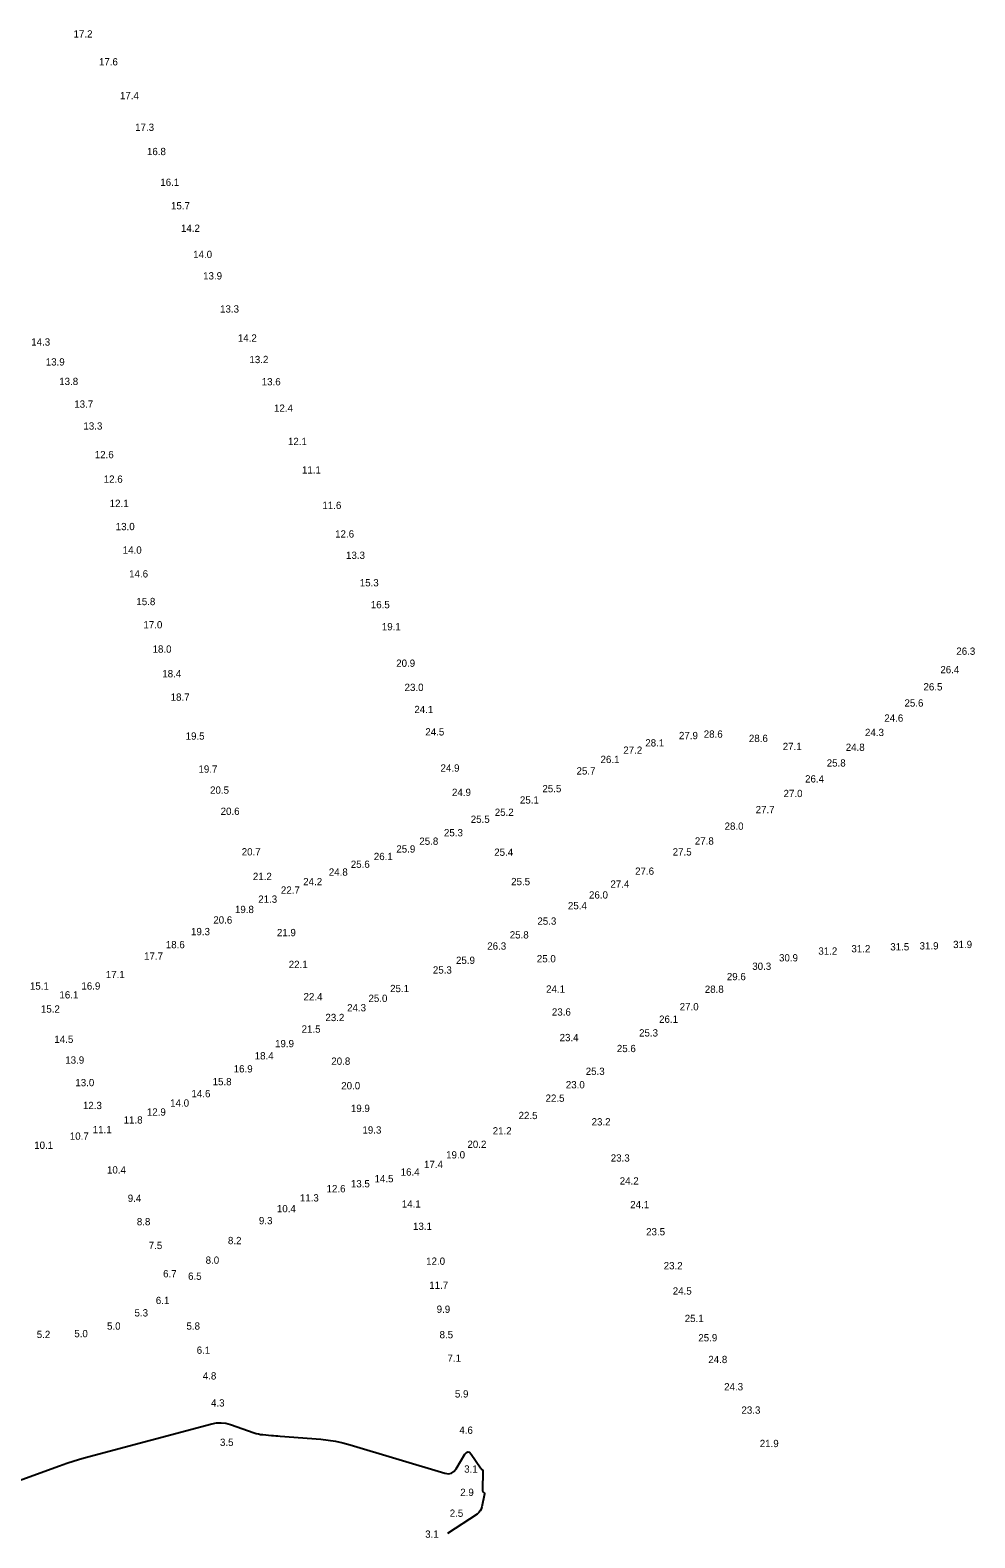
# Model space of a CAD drawing. Extents: x 837127 to 848654, y 3074248 to 3079868.
# Drawn here: x 848248 to 848654, y 3078663 to 3079310 of the extents above; entities that cross this region are included whole.
import ezdxf

# ---------------------------------------------------------------- set-up
doc = ezdxf.new("R2010")
doc.units = 0
doc.layers.add('V-HYDS-MAJR', color=7, linetype='Continuous')
doc.layers.add('V-HYDS-SOUN', color=7, linetype='Continuous')

msp = doc.modelspace()

# ---------------------------------------------------------------- linework, layer by layer
at = {"layer": 'V-HYDS-MAJR'}
msp.add_lwpolyline([(848242.88, 3078687.16), (848260.67, 3078693.63), (848263.82, 3078694.74), (848267, 3078695.78), (848270.19, 3078696.75), (848273.42, 3078697.64), (848325.98, 3078711.65), (848328.01, 3078712.03), (848330.03, 3078712.11), (848332.04, 3078711.88), (848334.04, 3078711.35), (848344.22, 3078707.8), (848345.12, 3078707.52), (848346.02, 3078707.3), (848346.94, 3078707.13), (848347.87, 3078707.01), (848351.61, 3078706.67), (848352.55, 3078706.58), (848353.49, 3078706.5), (848354.42, 3078706.43), (848355.36, 3078706.35), (848372.75, 3078705.02), (848375.95, 3078704.69), (848379.11, 3078704.19), (848382.24, 3078703.52), (848385.35, 3078702.68), (848426.1, 3078690.46), (848427.57, 3078690.23), (848428.86, 3078690.46), (848429.97, 3078691.16), (848430.9, 3078692.32), (848434.67, 3078698.61), (848435.3, 3078699.4), (848435.95, 3078699.68), (848436.62, 3078699.44), (848437.3, 3078698.69), (848441.36, 3078692.77), (848441.4, 3078692.71), (848441.45, 3078692.65), (848441.49, 3078692.59), (848441.54, 3078692.54), (848441.74, 3078692.31), (848441.79, 3078692.26), (848441.84, 3078692.21), (848441.9, 3078692.16), (848441.96, 3078692.12), (848442.27, 3078691.92), (848442.33, 3078691.87), (848442.37, 3078691.81), (848442.4, 3078691.74), (848442.4, 3078691.66), (848442.25, 3078682.89), (848442.26, 3078682.75), (848442.3, 3078682.62), (848442.37, 3078682.51), (848442.48, 3078682.42), (848442.95, 3078682.08), (848443.05, 3078681.98), (848443.11, 3078681.88), (848443.14, 3078681.75), (848443.13, 3078681.62), (848441.97, 3078676.02), (848441.69, 3078675.09), (848441.25, 3078674.27), (848440.65, 3078673.56), (848439.89, 3078672.95), (848427.24, 3078664.62)], dxfattribs=at)

# ---------------------------------------------------------------- texts
at = {"layer": 'V-HYDS-SOUN'}
for s, p in [('17.2 ', (848266.67, 3079306.65)), ('17.6 ', (848277.56, 3079294.68)), ('17.4 ', (848286.59, 3079280.17)), ('17.3 ', (848293.11, 3079266.59)), ('16.8 ', (848298.18, 3079256.18)), ('16.1 ', (848303.91, 3079242.97)), ('15.7 ', (848308.5, 3079232.91)), ('14.2 ', (848312.77, 3079223.24)), ('14.0 ', (848318.01, 3079212.01)), ('13.9 ', (848322.29, 3079202.81)), ('13.3 ', (848329.56, 3079188.61)), ('14.3 ', (848248.5, 3079174.43)), ('14.2 ', (848337.21, 3079176.13)), ('13.2 ', (848342.16, 3079166.9)), ('13.9 ', (848254.74, 3079165.88)), ('13.8 ', (848260.52, 3079157.5)), ('13.6 ', (848347.45, 3079157.37)), ('13.7 ', (848266.97, 3079147.76)), ('12.4 ', (848352.72, 3079146.02)), ('13.3 ', (848270.9, 3079138.37)), ('12.1 ', (848358.71, 3079131.73)), ('12.6 ', (848275.78, 3079126.09)), ('12.6 ', (848279.63, 3079115.56)), ('11.1 ', (848364.73, 3079119.5)), ('12.1 ', (848282.19, 3079105.17)), ('11.6 ', (848373.5, 3079104.31)), ('13.0 ', (848284.78, 3079095.21)), ('12.6 ', (848378.96, 3079092.04)), ('14.0 ', (848287.78, 3079085.12)), ('13.3 ', (848383.64, 3079082.88)), ('14.6 ', (848290.53, 3079074.91)), ('15.3 ', (848389.54, 3079071.1)), ('15.8 ', (848293.64, 3079063.03)), ('16.5 ', (848394.28, 3079061.7)), ('17.0 ', (848296.66, 3079053.04)), ('19.1 ', (848399.01, 3079052.24)), ('18.0 ', (848300.59, 3079042.63)), ('26.3 ', (848645.62, 3079041.72)), ('18.4 ', (848304.76, 3079032.05)), ('20.9 ', (848405.17, 3079036.56)), ('26.4 ', (848638.77, 3079033.79)), ('23.0 ', (848408.77, 3079026.19)), ('26.5 ', (848631.53, 3079026.43)), ('18.7 ', (848308.35, 3079021.99)), ('25.6 ', (848623.36, 3079019.49)), ('24.1 ', (848412.97, 3079016.69)), ('24.6 ', (848614.71, 3079012.99)), ('19.5 ', (848314.78, 3079005.3)), ('24.5 ', (848417.68, 3079007.09)), ('27.9 ', (848526.56, 3079005.5)), ('28.6 ', (848537.2, 3079006.14)), ('24.3 ', (848606.42, 3079006.84)), ('27.2 ', (848502.66, 3078999.23)), ('28.1 ', (848512.11, 3079002.37)), ('28.6 ', (848556.58, 3079004.29)), ('27.1 ', (848571.1, 3079000.82)), ('24.8 ', (848598.15, 3079000.47)), ('24.9 ', (848424.21, 3078991.57)), ('26.1 ', (848492.89, 3078995.26)), ('25.8 ', (848589.99, 3078993.74)), ('19.7 ', (848320.29, 3078991.11)), ('25.7 ', (848482.58, 3078990.33)), ('26.4 ', (848580.7, 3078986.91)), ('20.5 ', (848325.27, 3078982.1)), ('24.9 ', (848429.12, 3078981.12)), ('25.5 ', (848467.93, 3078982.72)), ('27.0 ', (848571.46, 3078980.64)), ('20.6 ', (848329.81, 3078973.01)), ('25.2 ', (848447.49, 3078972.59)), ('25.1 ', (848458.28, 3078977.85)), ('27.7 ', (848559.48, 3078973.71)), ('25.5 ', (848437.18, 3078969.59)), ('28.0 ', (848546.14, 3078966.62)), ('25.8 ', (848415.1, 3078960.16)), ('25.3 ', (848425.68, 3078963.81)), ('27.8 ', (848533.37, 3078960.25)), ('20.7 ', (848338.86, 3078955.6)), ('26.1 ', (848395.57, 3078953.61)), ('25.9 ', (848405.23, 3078956.83)), ('25.4 ', (848447.25, 3078955.44)), ('27.5 ', (848523.86, 3078955.57)), ('24.8 ', (848376.25, 3078946.91)), ('25.6 ', (848385.68, 3078950.26)), ('27.6 ', (848507.73, 3078947.3)), ('21.2 ', (848343.65, 3078945.04)), ('24.2 ', (848365.26, 3078942.82)), ('25.5 ', (848454.52, 3078942.83)), ('27.4 ', (848497.14, 3078941.77)), ('21.3 ', (848345.95, 3078935.29)), ('22.7 ', (848355.68, 3078939.18)), ('26.0 ', (848487.94, 3078937.1)), ('19.8 ', (848335.94, 3078930.86)), ('25.4 ', (848478.89, 3078932.49)), ('19.3 ', (848317.1, 3078921.37)), ('20.6 ', (848326.66, 3078926.35)), ('21.9 ', (848353.97, 3078920.94)), ('25.3 ', (848465.78, 3078925.86)), ('18.6 ', (848306.27, 3078915.77)), ('26.3 ', (848444.26, 3078915.16)), ('25.8 ', (848453.92, 3078919.96)), ('31.2 ', (848600.59, 3078914.01)), ('31.5 ', (848617.27, 3078914.84)), ('31.9 ', (848629.84, 3078915.24)), ('31.9 ', (848644.25, 3078915.84)), ('17.7 ', (848296.95, 3078910.87)), ('25.9 ', (848430.84, 3078909.04)), ('25.0 ', (848465.55, 3078909.73)), ('30.9 ', (848569.51, 3078910.12)), ('31.2 ', (848586.39, 3078913)), ('17.1 ', (848280.53, 3078902.94)), ('22.1 ', (848359.04, 3078907.27)), ('25.3 ', (848420.92, 3078904.89)), ('29.6 ', (848547.11, 3078902.05)), ('30.3 ', (848558.02, 3078906.49)), ('15.1 ', (848247.93, 3078898)), ('16.9 ', (848270.04, 3078898.02)), ('25.1 ', (848402.56, 3078896.93)), ('24.1 ', (848469.52, 3078896.7)), ('28.8 ', (848537.64, 3078896.63)), ('15.2 ', (848252.65, 3078888.14)), ('16.1 ', (848260.6, 3078894.21)), ('22.4 ', (848365.4, 3078893.41)), ('24.3 ', (848384.1, 3078888.68)), ('25.0 ', (848393.27, 3078892.72)), ('27.0 ', (848526.87, 3078889.13)), ('23.2 ', (848374.78, 3078884.5)), ('23.6 ', (848472.01, 3078886.86)), ('26.1 ', (848518.02, 3078883.76)), ('14.5 ', (848258.44, 3078875.14)), ('21.5 ', (848364.58, 3078879.53)), ('23.4 ', (848475.31, 3078875.88)), ('25.3 ', (848509.43, 3078877.89)), ('19.9 ', (848353.17, 3078873.29)), ('25.6 ', (848499.89, 3078871.18)), ('13.9 ', (848263.11, 3078866.23)), ('16.9 ', (848335.42, 3078862.47)), ('18.4 ', (848344.43, 3078868.05)), ('20.8 ', (848377.32, 3078865.75)), ('13.0 ', (848267.44, 3078856.55)), ('15.8 ', (848326.37, 3078856.96)), ('25.3 ', (848486.53, 3078861.4)), ('14.6 ', (848317.29, 3078851.83)), ('20.0 ', (848381.59, 3078855.22)), ('22.5 ', (848469.29, 3078849.87)), ('23.0 ', (848477.99, 3078855.64)), ('12.3 ', (848270.69, 3078846.73)), ('12.9 ', (848298.14, 3078843.93)), ('14.0 ', (848308.14, 3078847.79)), ('19.9 ', (848385.72, 3078845.48)), ('11.1 ', (848274.91, 3078836.38)), ('11.8 ', (848288.17, 3078840.53)), ('22.5 ', (848457.71, 3078842.43)), ('23.2 ', (848489.05, 3078839.71)), ('10.7 ', (848265.06, 3078833.59)), ('19.3 ', (848390.68, 3078836.21)), ('20.2 ', (848435.75, 3078830.07)), ('21.2 ', (848446.6, 3078835.84)), ('10.1 ', (848249.78, 3078829.67)), ('19.0 ', (848426.61, 3078825.56)), ('23.3 ', (848497.28, 3078824.2)), ('10.4 ', (848281.02, 3078819.08)), ('16.4 ', (848407.09, 3078818.18)), ('17.4 ', (848417.1, 3078821.41)), ('12.6 ', (848375.28, 3078811.02)), ('13.5 ', (848385.72, 3078813.15)), ('14.5 ', (848395.87, 3078815.32)), ('24.2 ', (848501.13, 3078814.35)), ('9.4', (848289.95, 3078806.92)), ('11.3 ', (848363.82, 3078807.08)), ('14.1 ', (848407.59, 3078804.45)), ('24.1 ', (848505.64, 3078804.19)), ('10.4 ', (848353.95, 3078802.47)), ('8.8', (848293.83, 3078796.86)), ('9.3', (848346.24, 3078797.31)), ('13.1 ', (848412.39, 3078794.88)), ('23.5 ', (848512.46, 3078792.55)), ('7.5', (848298.94, 3078786.65)), ('8.2', (848332.95, 3078788.76)), ('8.0', (848323.37, 3078780.35)), ('12.0 ', (848418.03, 3078779.91)), ('6.7', (848305.11, 3078774.52)), ('6.5', (848315.83, 3078773.46)), ('23.2 ', (848520, 3078777.97)), ('11.7 ', (848419.34, 3078769.57)), ('24.5 ', (848523.89, 3078767.11)), ('6.1', (848301.98, 3078763.05)), ('9.9', (848422.55, 3078759.29)), ('5.3', (848292.84, 3078757.73)), ('25.1 ', (848529.03, 3078755.33)), ('5.2', (848250.88, 3078748.46)), ('5.0', (848266.98, 3078748.82)), ('5.0', (848281.04, 3078752.07)), ('5.8', (848315.14, 3078752.07)), ('8.5', (848423.79, 3078748.37)), ('25.9 ', (848534.87, 3078747.05)), ('6.1', (848319.54, 3078741.71)), ('7.1', (848427.18, 3078738.27)), ('24.8 ', (848539.16, 3078737.71)), ('4.8', (848322.15, 3078730.68)), ('5.9', (848430.37, 3078722.94)), ('24.3 ', (848545.96, 3078726.01)), ('4.3', (848325.67, 3078719.07)), ('23.3 ', (848553.38, 3078715.99)), ('4.6', (848432.28, 3078707.37)), ('3.5', (848329.53, 3078702.17)), ('21.9 ', (848561.24, 3078701.66)), ('3.1', (848434.36, 3078690.7)), ('2.9', (848432.67, 3078680.69)), ('2.5', (848428.15, 3078671.74)), ('3.1', (848417.61, 3078662.76))]:
    msp.add_text(s, height=3.125, dxfattribs=at).set_placement(p)

doc.saveas('drawing.dxf')
